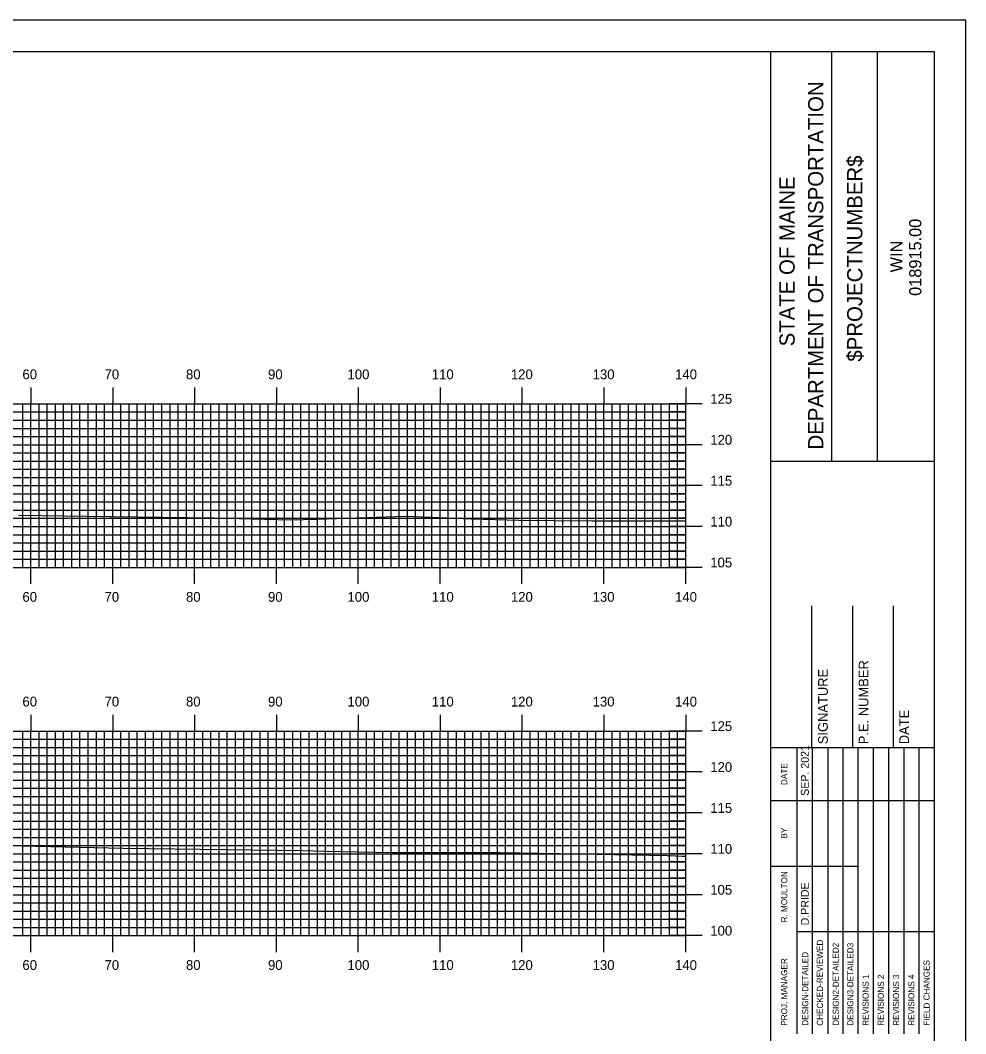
# Model space of a CAD drawing. Extents: x 1779893 to 1780236, y 442591 to 442811.
# Drawn here: x 1780117.1 to 1780232.6, y 442686.7 to 442810.5 of the extents above; entities that cross this region are included whole.
import ezdxf

# ---------------------------------------------------------------- set-up
doc = ezdxf.new("R2010")
doc.units = 0
for name, color, linetype in [('BORDER', 7, 'Continuous'), ('H_V ANNOTATION', 7, 'Continuous'), ('MAJOR', 7, 'Continuous'), ('MINOR', 7, 'Continuous'), ('PLOT BOUNDARY', 7, 'Continuous'), ('S_Roadway_Centerline', 7, 'Continuous')]:
    doc.layers.add(name, color=color, linetype=linetype)

msp = doc.modelspace()

# ---------------------------------------------------------------- linework, layer by layer
at = {"layer": 'BORDER'}
for p, q in [((1780208.76, 442596.67), (1780208.76, 442806.67)), ((1780216.21, 442756.66), (1780216.21, 442806.66)), ((1780221.8, 442756.66), (1780221.8, 442806.66)), ((1780208.76, 442756.65), (1780228.76, 442756.65)), ((1780213.76, 442721.67), (1780213.76, 442738.97)), ((1780218.76, 442721.67), (1780218.76, 442738.97)), ((1780223.76, 442721.67), (1780223.76, 442738.97)), ((1780208.76, 442721.67), (1780228.76, 442721.67))]:
    msp.add_line(p, q, dxfattribs=at)
msp.add_lwpolyline([(1779908.76, 442596.67), (1780228.76, 442596.67), (1780228.76, 442806.67), (1779908.76, 442806.67)], close=True, dxfattribs=at)
for points in [[(1780211.99, 442715.17), (1780211.99, 442721.67)], [(1780213.85, 442686.68), (1780213.85, 442721.67)], [(1780215.71, 442721.67), (1780215.71, 442686.68)], [(1780217.58, 442686.68), (1780217.58, 442721.67)], [(1780219.44, 442686.68), (1780219.44, 442721.67)], [(1780221.3, 442686.68), (1780221.3, 442721.67)], [(1780223.17, 442686.68), (1780223.17, 442721.67)], [(1780225.03, 442686.68), (1780225.03, 442721.67)], [(1780226.89, 442686.68), (1780226.89, 442721.67)], [(1780211.99, 442686.68), (1780211.99, 442720.26)], [(1780208.76, 442715.17), (1780228.76, 442715.17)], [(1780208.76, 442707.17), (1780211.99, 442707.17)], [(1780211.99, 442707.17), (1780219.44, 442707.17)], [(1780211.99, 442699.17), (1780228.76, 442699.17)]]:
    msp.add_lwpolyline(points, dxfattribs=at)
at = {"layer": 'MAJOR'}
for p, q in [((1780118.36, 442765.67), (1780118.36, 442763.67)), ((1780128.36, 442765.67), (1780128.36, 442763.67)), ((1780138.36, 442765.67), (1780138.36, 442763.67)), ((1780148.36, 442765.67), (1780148.36, 442763.67)), ((1780158.36, 442765.67), (1780158.36, 442763.67)), ((1780168.36, 442765.67), (1780168.36, 442763.67)), ((1780178.36, 442765.67), (1780178.36, 442763.67)), ((1780188.36, 442765.67), (1780188.36, 442763.67)), ((1780198.36, 442765.67), (1780198.36, 442763.67)), ((1779918.36, 442763.67), (1780198.36, 442763.67)), ((1779918.36, 442763.67), (1780198.36, 442763.67)), ((1780118.36, 442743.67), (1780118.36, 442763.67)), ((1780128.36, 442743.67), (1780128.36, 442763.67)), ((1780138.36, 442743.67), (1780138.36, 442763.67)), ((1780148.36, 442743.67), (1780148.36, 442763.67)), ((1780158.36, 442743.67), (1780158.36, 442763.67)), ((1780168.36, 442743.67), (1780168.36, 442763.67)), ((1780178.36, 442743.67), (1780178.36, 442763.67)), ((1780188.36, 442743.67), (1780188.36, 442763.67)), ((1780200.36, 442763.67), (1780196.35, 442763.67)), ((1780198.36, 442743.67), (1780198.36, 442763.67)), ((1780198.36, 442743.67), (1780198.36, 442763.67)), ((1779918.36, 442758.67), (1780198.36, 442758.67)), ((1780200.36, 442758.67), (1780196.35, 442758.67)), ((1779918.36, 442753.67), (1780198.36, 442753.67)), ((1780200.36, 442753.67), (1780196.35, 442753.67)), ((1779918.36, 442748.67), (1780198.36, 442748.67)), ((1780200.36, 442748.67), (1780196.35, 442748.67)), ((1779918.36, 442743.67), (1780198.36, 442743.67)), ((1779918.36, 442743.67), (1780198.36, 442743.67)), ((1780118.36, 442741.66), (1780118.36, 442743.67)), ((1780128.36, 442741.66), (1780128.36, 442743.67)), ((1780138.36, 442741.66), (1780138.36, 442743.67)), ((1780148.36, 442741.66), (1780148.36, 442743.67)), ((1780158.36, 442741.66), (1780158.36, 442743.67)), ((1780168.36, 442741.66), (1780168.36, 442743.67)), ((1780178.36, 442741.66), (1780178.36, 442743.67)), ((1780188.36, 442741.66), (1780188.36, 442743.67)), ((1780200.36, 442743.67), (1780196.35, 442743.67)), ((1780198.36, 442741.66), (1780198.36, 442743.67)), ((1780118.36, 442725.67), (1780118.36, 442723.67)), ((1780128.36, 442725.67), (1780128.36, 442723.67)), ((1780138.36, 442725.67), (1780138.36, 442723.67)), ((1780148.36, 442725.67), (1780148.36, 442723.67)), ((1780158.36, 442725.67), (1780158.36, 442723.67)), ((1780168.36, 442725.67), (1780168.36, 442723.67)), ((1780178.36, 442725.67), (1780178.36, 442723.67)), ((1780188.36, 442725.67), (1780188.36, 442723.67)), ((1780198.36, 442725.67), (1780198.36, 442723.67)), ((1779918.36, 442723.67), (1780198.36, 442723.67)), ((1779918.36, 442723.67), (1780198.36, 442723.67)), ((1780118.36, 442698.67), (1780118.36, 442723.67)), ((1780128.36, 442698.67), (1780128.36, 442723.67)), ((1780138.36, 442698.67), (1780138.36, 442723.67)), ((1780148.36, 442698.67), (1780148.36, 442723.67)), ((1780158.36, 442698.67), (1780158.36, 442723.67)), ((1780168.36, 442698.67), (1780168.36, 442723.67)), ((1780178.36, 442698.67), (1780178.36, 442723.67)), ((1780188.36, 442698.67), (1780188.36, 442723.67)), ((1780200.36, 442723.67), (1780196.35, 442723.67)), ((1780198.36, 442698.67), (1780198.36, 442723.67)), ((1780198.36, 442698.67), (1780198.36, 442723.67)), ((1779918.36, 442718.67), (1780198.36, 442718.67)), ((1780200.36, 442718.67), (1780196.35, 442718.67)), ((1779918.36, 442713.67), (1780198.36, 442713.67)), ((1780200.36, 442713.67), (1780196.35, 442713.67)), ((1779918.36, 442708.67), (1780198.36, 442708.67)), ((1780200.36, 442708.67), (1780196.35, 442708.67)), ((1779918.36, 442703.67), (1780198.36, 442703.67)), ((1780200.36, 442703.67), (1780196.35, 442703.67)), ((1779918.36, 442698.67), (1780198.36, 442698.67)), ((1779918.36, 442698.67), (1780198.36, 442698.67)), ((1780118.36, 442696.66), (1780118.36, 442698.67)), ((1780128.36, 442696.66), (1780128.36, 442698.67)), ((1780138.36, 442696.66), (1780138.36, 442698.67)), ((1780148.36, 442696.66), (1780148.36, 442698.67)), ((1780158.36, 442696.66), (1780158.36, 442698.67)), ((1780168.36, 442696.66), (1780168.36, 442698.67)), ((1780178.36, 442696.66), (1780178.36, 442698.67)), ((1780188.36, 442696.66), (1780188.36, 442698.67)), ((1780200.36, 442698.67), (1780196.35, 442698.67)), ((1780198.36, 442696.66), (1780198.36, 442698.67))]:
    msp.add_line(p, q, dxfattribs=at)
at = {"layer": 'MINOR'}
for p, q in [((1780117.36, 442743.67), (1780117.36, 442763.67)), ((1780119.36, 442743.67), (1780119.36, 442763.67)), ((1780120.36, 442743.67), (1780120.36, 442763.67)), ((1780121.36, 442743.67), (1780121.36, 442763.67)), ((1780122.36, 442743.67), (1780122.36, 442763.67)), ((1780123.36, 442743.67), (1780123.36, 442763.67)), ((1780124.36, 442743.67), (1780124.36, 442763.67)), ((1780125.36, 442743.67), (1780125.36, 442763.67)), ((1780126.36, 442743.67), (1780126.36, 442763.67)), ((1780127.36, 442743.67), (1780127.36, 442763.67)), ((1780129.36, 442743.67), (1780129.36, 442763.67)), ((1780130.36, 442743.67), (1780130.36, 442763.67)), ((1780131.36, 442743.67), (1780131.36, 442763.67)), ((1780132.36, 442743.67), (1780132.36, 442763.67)), ((1780133.36, 442743.67), (1780133.36, 442763.67)), ((1780134.36, 442743.67), (1780134.36, 442763.67)), ((1780135.36, 442743.67), (1780135.36, 442763.67)), ((1780136.36, 442743.67), (1780136.36, 442763.67)), ((1780137.36, 442743.67), (1780137.36, 442763.67)), ((1780139.36, 442743.67), (1780139.36, 442763.67)), ((1780140.36, 442743.67), (1780140.36, 442763.67)), ((1780141.36, 442743.67), (1780141.36, 442763.67)), ((1780142.36, 442743.67), (1780142.36, 442763.67)), ((1780143.36, 442743.67), (1780143.36, 442763.67)), ((1780144.36, 442743.67), (1780144.36, 442763.67)), ((1780145.36, 442743.67), (1780145.36, 442763.67)), ((1780146.36, 442743.67), (1780146.36, 442763.67)), ((1780147.36, 442743.67), (1780147.36, 442763.67)), ((1780149.36, 442743.67), (1780149.36, 442763.67)), ((1780150.36, 442743.67), (1780150.36, 442763.67)), ((1780151.36, 442743.67), (1780151.36, 442763.67)), ((1780152.36, 442743.67), (1780152.36, 442763.67)), ((1780153.36, 442743.67), (1780153.36, 442763.67)), ((1780154.36, 442743.67), (1780154.36, 442763.67)), ((1780155.36, 442743.67), (1780155.36, 442763.67)), ((1780156.36, 442743.67), (1780156.36, 442763.67)), ((1780157.36, 442743.67), (1780157.36, 442763.67)), ((1780159.36, 442743.67), (1780159.36, 442763.67)), ((1780160.36, 442743.67), (1780160.36, 442763.67)), ((1780161.36, 442743.67), (1780161.36, 442763.67)), ((1780162.36, 442743.67), (1780162.36, 442763.67)), ((1780163.36, 442743.67), (1780163.36, 442763.67)), ((1780164.36, 442743.67), (1780164.36, 442763.67)), ((1780165.36, 442743.67), (1780165.36, 442763.67)), ((1780166.36, 442743.67), (1780166.36, 442763.67)), ((1780167.36, 442743.67), (1780167.36, 442763.67)), ((1780169.36, 442743.67), (1780169.36, 442763.67)), ((1780170.36, 442743.67), (1780170.36, 442763.67)), ((1780171.36, 442743.67), (1780171.36, 442763.67)), ((1780172.36, 442743.67), (1780172.36, 442763.67)), ((1780173.36, 442743.67), (1780173.36, 442763.67)), ((1780174.36, 442743.67), (1780174.36, 442763.67)), ((1780175.36, 442743.67), (1780175.36, 442763.67)), ((1780176.36, 442743.67), (1780176.36, 442763.67)), ((1780177.36, 442743.67), (1780177.36, 442763.67)), ((1780179.36, 442743.67), (1780179.36, 442763.67)), ((1780180.36, 442743.67), (1780180.36, 442763.67)), ((1780181.36, 442743.67), (1780181.36, 442763.67)), ((1780182.36, 442743.67), (1780182.36, 442763.67)), ((1780183.36, 442743.67), (1780183.36, 442763.67)), ((1780184.36, 442743.67), (1780184.36, 442763.67)), ((1780185.36, 442743.67), (1780185.36, 442763.67)), ((1780186.36, 442743.67), (1780186.36, 442763.67)), ((1780187.36, 442743.67), (1780187.36, 442763.67)), ((1780189.36, 442743.67), (1780189.36, 442763.67)), ((1780190.36, 442743.67), (1780190.36, 442763.67)), ((1780191.36, 442743.67), (1780191.36, 442763.67)), ((1780192.36, 442743.67), (1780192.36, 442763.67)), ((1780193.36, 442743.67), (1780193.36, 442763.67)), ((1780194.36, 442743.67), (1780194.36, 442763.67)), ((1780195.36, 442743.67), (1780195.36, 442763.67)), ((1780196.36, 442743.67), (1780196.36, 442763.67)), ((1780197.36, 442743.67), (1780197.36, 442763.67)), ((1779918.36, 442762.67), (1780198.36, 442762.67)), ((1780198.36, 442762.67), (1780196.35, 442762.67)), ((1779918.36, 442761.67), (1780198.36, 442761.67)), ((1780198.36, 442761.67), (1780196.35, 442761.67)), ((1779918.36, 442760.67), (1780198.36, 442760.67)), ((1780198.36, 442760.67), (1780196.35, 442760.67)), ((1779918.36, 442759.67), (1780198.36, 442759.67)), ((1780198.36, 442759.67), (1780196.35, 442759.67)), ((1779918.36, 442757.67), (1780198.36, 442757.67)), ((1780198.36, 442757.67), (1780196.35, 442757.67)), ((1779918.36, 442756.67), (1780198.36, 442756.67)), ((1780198.36, 442756.67), (1780196.35, 442756.67)), ((1779918.36, 442755.67), (1780198.36, 442755.67)), ((1780198.36, 442755.67), (1780196.35, 442755.67)), ((1779918.36, 442754.67), (1780198.36, 442754.67)), ((1780198.36, 442754.67), (1780196.35, 442754.67)), ((1779918.36, 442752.67), (1780198.36, 442752.67)), ((1780198.36, 442752.67), (1780196.35, 442752.67)), ((1779918.36, 442751.67), (1780198.36, 442751.67)), ((1780198.36, 442751.67), (1780196.35, 442751.67)), ((1779918.36, 442750.67), (1780198.36, 442750.67)), ((1780198.36, 442750.67), (1780196.35, 442750.67)), ((1779918.36, 442749.67), (1780198.36, 442749.67)), ((1780198.36, 442749.67), (1780196.35, 442749.67)), ((1779918.36, 442747.67), (1780198.36, 442747.67)), ((1780198.36, 442747.67), (1780196.35, 442747.67)), ((1779918.36, 442746.67), (1780198.36, 442746.67)), ((1780198.36, 442746.67), (1780196.35, 442746.67)), ((1779918.36, 442745.67), (1780198.36, 442745.67)), ((1780198.36, 442745.67), (1780196.35, 442745.67)), ((1779918.36, 442744.67), (1780198.36, 442744.67)), ((1780198.36, 442744.67), (1780196.35, 442744.67)), ((1780117.36, 442698.67), (1780117.36, 442723.67)), ((1780119.36, 442698.67), (1780119.36, 442723.67)), ((1780120.36, 442698.67), (1780120.36, 442723.67)), ((1780121.36, 442698.67), (1780121.36, 442723.67)), ((1780122.36, 442698.67), (1780122.36, 442723.67)), ((1780123.36, 442698.67), (1780123.36, 442723.67)), ((1780124.36, 442698.67), (1780124.36, 442723.67)), ((1780125.36, 442698.67), (1780125.36, 442723.67)), ((1780126.36, 442698.67), (1780126.36, 442723.67)), ((1780127.36, 442698.67), (1780127.36, 442723.67)), ((1780129.36, 442698.67), (1780129.36, 442723.67)), ((1780130.36, 442698.67), (1780130.36, 442723.67)), ((1780131.36, 442698.67), (1780131.36, 442723.67)), ((1780132.36, 442698.67), (1780132.36, 442723.67)), ((1780133.36, 442698.67), (1780133.36, 442723.67)), ((1780134.36, 442698.67), (1780134.36, 442723.67)), ((1780135.36, 442698.67), (1780135.36, 442723.67)), ((1780136.36, 442698.67), (1780136.36, 442723.67)), ((1780137.36, 442698.67), (1780137.36, 442723.67)), ((1780139.36, 442698.67), (1780139.36, 442723.67)), ((1780140.36, 442698.67), (1780140.36, 442723.67)), ((1780141.36, 442698.67), (1780141.36, 442723.67)), ((1780142.36, 442698.67), (1780142.36, 442723.67)), ((1780143.36, 442698.67), (1780143.36, 442723.67)), ((1780144.36, 442698.67), (1780144.36, 442723.67)), ((1780145.36, 442698.67), (1780145.36, 442723.67)), ((1780146.36, 442698.67), (1780146.36, 442723.67)), ((1780147.36, 442698.67), (1780147.36, 442723.67)), ((1780149.36, 442698.67), (1780149.36, 442723.67)), ((1780150.36, 442698.67), (1780150.36, 442723.67)), ((1780151.36, 442698.67), (1780151.36, 442723.67)), ((1780152.36, 442698.67), (1780152.36, 442723.67)), ((1780153.36, 442698.67), (1780153.36, 442723.67)), ((1780154.36, 442698.67), (1780154.36, 442723.67)), ((1780155.36, 442698.67), (1780155.36, 442723.67)), ((1780156.36, 442698.67), (1780156.36, 442723.67)), ((1780157.36, 442698.67), (1780157.36, 442723.67)), ((1780159.36, 442698.67), (1780159.36, 442723.67)), ((1780160.36, 442698.67), (1780160.36, 442723.67)), ((1780161.36, 442698.67), (1780161.36, 442723.67)), ((1780162.36, 442698.67), (1780162.36, 442723.67)), ((1780163.36, 442698.67), (1780163.36, 442723.67)), ((1780164.36, 442698.67), (1780164.36, 442723.67)), ((1780165.36, 442698.67), (1780165.36, 442723.67)), ((1780166.36, 442698.67), (1780166.36, 442723.67)), ((1780167.36, 442698.67), (1780167.36, 442723.67)), ((1780169.36, 442698.67), (1780169.36, 442723.67)), ((1780170.36, 442698.67), (1780170.36, 442723.67)), ((1780171.36, 442698.67), (1780171.36, 442723.67)), ((1780172.36, 442698.67), (1780172.36, 442723.67)), ((1780173.36, 442698.67), (1780173.36, 442723.67)), ((1780174.36, 442698.67), (1780174.36, 442723.67)), ((1780175.36, 442698.67), (1780175.36, 442723.67)), ((1780176.36, 442698.67), (1780176.36, 442723.67)), ((1780177.36, 442698.67), (1780177.36, 442723.67)), ((1780179.36, 442698.67), (1780179.36, 442723.67)), ((1780180.36, 442698.67), (1780180.36, 442723.67)), ((1780181.36, 442698.67), (1780181.36, 442723.67)), ((1780182.36, 442698.67), (1780182.36, 442723.67)), ((1780183.36, 442698.67), (1780183.36, 442723.67)), ((1780184.36, 442698.67), (1780184.36, 442723.67)), ((1780185.36, 442698.67), (1780185.36, 442723.67)), ((1780186.36, 442698.67), (1780186.36, 442723.67)), ((1780187.36, 442698.67), (1780187.36, 442723.67)), ((1780189.36, 442698.67), (1780189.36, 442723.67)), ((1780190.36, 442698.67), (1780190.36, 442723.67)), ((1780191.36, 442698.67), (1780191.36, 442723.67)), ((1780192.36, 442698.67), (1780192.36, 442723.67)), ((1780193.36, 442698.67), (1780193.36, 442723.67)), ((1780194.36, 442698.67), (1780194.36, 442723.67)), ((1780195.36, 442698.67), (1780195.36, 442723.67)), ((1780196.36, 442698.67), (1780196.36, 442723.67)), ((1780197.36, 442698.67), (1780197.36, 442723.67)), ((1779918.36, 442722.67), (1780198.36, 442722.67)), ((1779918.36, 442721.67), (1780198.36, 442721.67)), ((1780198.36, 442722.67), (1780196.35, 442722.67)), ((1780198.36, 442721.67), (1780196.35, 442721.67)), ((1779918.36, 442720.67), (1780198.36, 442720.67)), ((1780198.36, 442720.67), (1780196.35, 442720.67)), ((1779918.36, 442719.67), (1780198.36, 442719.67)), ((1780198.36, 442719.67), (1780196.35, 442719.67)), ((1779918.36, 442717.67), (1780198.36, 442717.67)), ((1779918.36, 442716.67), (1780198.36, 442716.67)), ((1780198.36, 442717.67), (1780196.35, 442717.67)), ((1780198.36, 442716.67), (1780196.35, 442716.67)), ((1779918.36, 442715.67), (1780198.36, 442715.67)), ((1780198.36, 442715.67), (1780196.35, 442715.67)), ((1779918.36, 442714.67), (1780198.36, 442714.67)), ((1780198.36, 442714.67), (1780196.35, 442714.67)), ((1779918.36, 442712.67), (1780198.36, 442712.67)), ((1779918.36, 442711.67), (1780198.36, 442711.67)), ((1780198.36, 442712.67), (1780196.35, 442712.67)), ((1780198.36, 442711.67), (1780196.35, 442711.67)), ((1779918.36, 442710.67), (1780198.36, 442710.67)), ((1780198.36, 442710.67), (1780196.35, 442710.67)), ((1779918.36, 442709.67), (1780198.36, 442709.67)), ((1780198.36, 442709.67), (1780196.35, 442709.67)), ((1779918.36, 442707.67), (1780198.36, 442707.67)), ((1779918.36, 442706.67), (1780198.36, 442706.67)), ((1780198.36, 442707.67), (1780196.35, 442707.67)), ((1780198.36, 442706.67), (1780196.35, 442706.67)), ((1779918.36, 442705.67), (1780198.36, 442705.67)), ((1780198.36, 442705.67), (1780196.35, 442705.67)), ((1779918.36, 442704.67), (1780198.36, 442704.67)), ((1780198.36, 442704.67), (1780196.35, 442704.67)), ((1779918.36, 442702.67), (1780198.36, 442702.67)), ((1779918.36, 442701.67), (1780198.36, 442701.67)), ((1780198.36, 442702.67), (1780196.35, 442702.67)), ((1780198.36, 442701.67), (1780196.35, 442701.67)), ((1779918.36, 442700.67), (1780198.36, 442700.67)), ((1780198.36, 442700.67), (1780196.35, 442700.67)), ((1779918.36, 442699.67), (1780198.36, 442699.67)), ((1780198.36, 442699.67), (1780196.35, 442699.67))]:
    msp.add_line(p, q, dxfattribs=at)
at = {"layer": 'PLOT BOUNDARY'}
msp.add_lwpolyline([(1779892.57, 442590.55), (1780232.57, 442590.55), (1780232.57, 442810.55), (1779892.57, 442810.55)], close=True, dxfattribs=at)
at = {"layer": 'S_Roadway_Centerline'}
for points in [[(1780116.83, 442750.05), (1780128.02, 442749.91), (1780128.11, 442749.91), (1780128.22, 442749.91), (1780140.68, 442749.75), (1780150.08, 442749.5), (1780153.31, 442749.55), (1780164.18, 442749.95), (1780172.14, 442749.62), (1780177.98, 442749.45), (1780186.91, 442749.38), (1780195.14, 442749.36), (1780197.74, 442749.35), (1780198.36, 442749.37)], [(1780108.34, 442709.83), (1780126.08, 442709.42), (1780127.87, 442709.39), (1780129.69, 442709.36), (1780151.54, 442709.08), (1780154.2, 442709), (1780162.52, 442708.83), (1780175.69, 442708.81), (1780185.36, 442708.65), (1780196.1, 442708.44), (1780197.12, 442708.4), (1780197.92, 442708.39), (1780198.36, 442708.39)]]:
    msp.add_lwpolyline(points, dxfattribs=at)

# ---------------------------------------------------------------- texts
at = {"layer": 'BORDER'}
for s, height, p in [('DEPARTMENT OF TRANSPORTATION', 1.8635, (1780215.17, 442758.08)), ('$PROJECTNUMBER$', 1.8635, (1780219.94, 442768.82)), ('STATE OF MAINE', 1.8635, (1780211.67, 442770.69)), ('018915.00', 1.491, (1780227.15, 442776.86)), ('WIN', 1.491, (1780224.83, 442779.73)), ('P.E. NUMBER', 1.1811, (1780220.68, 442722.06)), ('SIGNATURE', 1.181, (1780215.72, 442722.06)), ('DATE', 1.181, (1780225.64, 442722.06)), ('SEP. 2021', 0.969, (1780213.4, 442715.76)), ('DATE', 0.743, (1780210.76, 442717.08)), ('BY', 0.743, (1780210.76, 442710.54)), ('R. MOULTON', 0.745, (1780210.76, 442700.28)), ('D.PRIDE', 0.969, (1780213.4, 442699.92)), ('CHECKED-REVIEWED', 0.7455, (1780215.12, 442687.65)), ('DESIGN2-DETAILED2', 0.7455, (1780217.06, 442687.65)), ('DESIGN3-DETAILED3', 0.7455, (1780218.84, 442687.65)), ('PROJ. MANAGER', 0.7455, (1780210.76, 442687.65)), ('DESIGN-DETAILED', 0.7455, (1780213.33, 442687.65)), ('FIELD CHANGES', 0.7455, (1780228.16, 442687.65)), ('REVISIONS 1', 0.7455, (1780220.71, 442687.65)), ('REVISIONS 2', 0.7455, (1780222.57, 442687.65)), ('REVISIONS 3', 0.7455, (1780224.43, 442687.65)), ('REVISIONS 4', 0.7455, (1780226.3, 442687.65))]:
    msp.add_text(s, height=height, rotation=90, dxfattribs=at).set_placement(p)
at = {"layer": 'H_V ANNOTATION'}
for s, p in [('60', (1780117.33, 442766.67)), ('70', (1780127.36, 442766.67)), ('80', (1780137.31, 442766.67)), ('90', (1780147.33, 442766.67)), ('100', (1780157.04, 442766.67)), ('110', (1780167.34, 442766.67)), ('120', (1780177, 442766.67)), ('130', (1780186.99, 442766.67)), ('140', (1780197.06, 442766.67)), ('125', (1780201.36, 442763.67)), ('120', (1780201.36, 442758.67)), ('115', (1780201.36, 442753.67)), ('110', (1780201.36, 442748.67)), ('105', (1780201.36, 442743.67)), ('60', (1780117.33, 442739.47)), ('70', (1780127.36, 442739.47)), ('80', (1780137.31, 442739.47)), ('90', (1780147.33, 442739.47)), ('100', (1780157.04, 442739.47)), ('110', (1780167.34, 442739.47)), ('120', (1780177, 442739.47)), ('130', (1780186.99, 442739.47)), ('140', (1780197.06, 442739.47)), ('60', (1780117.33, 442726.67)), ('70', (1780127.36, 442726.67)), ('80', (1780137.31, 442726.67)), ('90', (1780147.33, 442726.67)), ('100', (1780157.04, 442726.67)), ('110', (1780167.34, 442726.67)), ('120', (1780177, 442726.67)), ('130', (1780186.99, 442726.67)), ('140', (1780197.06, 442726.67)), ('125', (1780201.36, 442723.67)), ('120', (1780201.36, 442718.67)), ('115', (1780201.36, 442713.67)), ('110', (1780201.36, 442708.67)), ('105', (1780201.36, 442703.67)), ('100', (1780201.36, 442698.67)), ('60', (1780117.33, 442694.47)), ('70', (1780127.36, 442694.47)), ('80', (1780137.31, 442694.47)), ('90', (1780147.33, 442694.47)), ('100', (1780157.04, 442694.47)), ('110', (1780167.34, 442694.47)), ('120', (1780177, 442694.47)), ('130', (1780186.99, 442694.47)), ('140', (1780197.06, 442694.47))]:
    msp.add_text(s, height=1.2, dxfattribs=at).set_placement(p)

doc.saveas('drawing.dxf')
